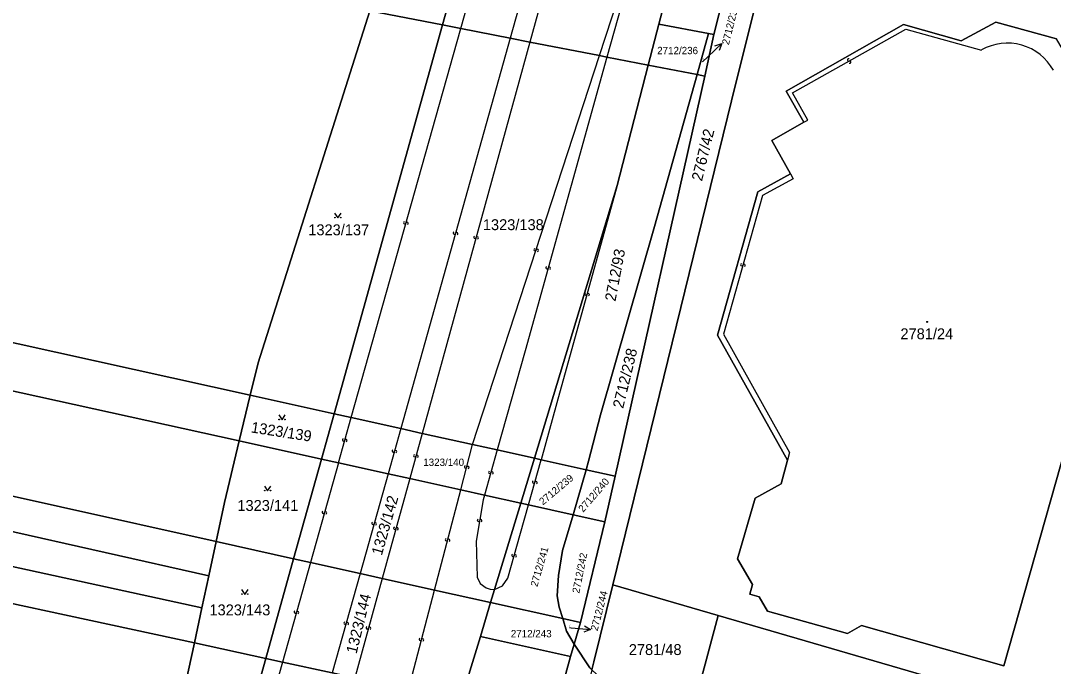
# Model space of a CAD drawing. Extents: x -596024 to -594475, y -1163820 to -1161957.
# Drawn here: x -595458.9 to -595298.2, y -1162184.4 to -1162083.9 of the extents above; entities that cross this region are included whole.
import ezdxf

# ---------------------------------------------------------------- set-up
doc = ezdxf.new("R2010")
doc.units = 0
for name, color, linetype in [('Level 1', 7, 'Continuous'), ('Level 13', 7, 'Continuous'), ('Level 3', 7, 'Continuous'), ('Level 4', 7, 'Continuous'), ('Level 5', 7, 'Continuous'), ('Level 57', 7, 'Continuous'), ('Level 60', 7, 'Continuous')]:
    doc.layers.add(name, color=color, linetype=linetype)

msp = doc.modelspace()

# ---------------------------------------------------------------- linework, layer by layer
at = {"layer": 'Level 1'}
for points in [[(-595366.74, -1162171.69), (-595347.56, -1162093.56), (-595333.91, -1162039.19), (-595332.78, -1162034.85)], [(-595385.78, -1162057.72), (-595393.25, -1162084.52)], [(-595359.57, -1162084.4), (-595354.15, -1162063.7)], [(-595351, -1162086.03), (-595345.7, -1162065.12)], [(-595404.57, -1162082.31), (-595421.96, -1162137.12), (-595423.19, -1162142.18)], [(-595393.25, -1162084.52), (-595404.57, -1162082.31)], [(-595393.25, -1162084.52), (-595410.14, -1162145.07)], [(-595393.25, -1162084.52), (-595390.42, -1162085.07)], [(-595390.42, -1162085.07), (-595382.7, -1162086.58)], [(-595361.22, -1162090.78), (-595359.57, -1162084.4)], [(-595359.57, -1162084.4), (-595351.83, -1162085.86)], [(-595255.68, -1162115.98), (-595277.18, -1162109.81), (-595285.73, -1162094.54), (-595294.54, -1162092.05), (-595297.65, -1162086.67), (-595307.1, -1162084.06), (-595312.49, -1162087.01), (-595321.47, -1162084.47), (-595339.77, -1162094.82), (-595336.98, -1162099.67)], [(-595382.7, -1162086.58), (-595379.64, -1162087.18)], [(-595379.64, -1162087.18), (-595368.8, -1162089.3)], [(-595351.83, -1162085.86), (-595353.63, -1162092.26)], [(-595352.42, -1162092.5), (-595351, -1162086.03)], [(-595351.83, -1162085.86), (-595351, -1162086.03)], [(-595368.8, -1162089.3), (-595367.65, -1162089.52)], [(-595367.65, -1162089.52), (-595361.22, -1162090.78)], [(-595366.06, -1162109.54), (-595361.22, -1162090.78)], [(-595361.22, -1162090.78), (-595353.63, -1162092.26)], [(-595370.9, -1162153.77), (-595370.51, -1162152.44), (-595368.66, -1162145.25), (-595360.26, -1162115.92), (-595353.63, -1162092.26)], [(-595352.42, -1162092.5), (-595366.35, -1162154.78)], [(-595353.63, -1162092.26), (-595352.42, -1162092.5)], [(-595336.98, -1162099.67), (-595341.96, -1162102.49), (-595339.09, -1162107.72)], [(-595339.09, -1162107.72), (-595344.15, -1162110.52), (-595350.46, -1162132.83), (-595339.54, -1162152.29)], [(-595378.94, -1162151.99), (-595366.06, -1162109.54)], [(-595529.52, -1162117.18), (-595471.58, -1162131.45), (-595423.19, -1162142.18)], [(-595424.9, -1162149.3), (-595473.29, -1162138.61), (-595531.85, -1162124.44)], [(-595608.74, -1162129.27), (-595574.69, -1162137.44), (-595478.13, -1162159.4), (-595429.64, -1162170.28)], [(-595430.71, -1162175.3), (-595479.35, -1162164.7), (-595575.71, -1162142.44), (-595610.67, -1162134.07)], [(-595339.54, -1162152.29), (-595340.54, -1162155.98), (-595344.6, -1162158.19), (-595347.3, -1162167.65), (-595344.98, -1162171.66), (-595345.4, -1162173.16), (-595343.93, -1162173.56), (-595342.65, -1162175.78), (-595330.22, -1162179.25), (-595328.01, -1162178.03), (-595305.84, -1162184.29), (-595292.09, -1162135.75)], [(-595536.86, -1162140.03), (-595477.03, -1162154.15), (-595428.5, -1162164.95)], [(-595423.19, -1162142.18), (-595424.9, -1162149.3)], [(-595410.14, -1162145.07), (-595423.19, -1162142.18)], [(-595412.11, -1162152.13), (-595410.14, -1162145.07)], [(-595410.14, -1162145.07), (-595407.49, -1162145.66)], [(-595407.49, -1162145.66), (-595399.75, -1162147.37)], [(-595399.75, -1162147.37), (-595396.42, -1162148.11)], [(-595396.42, -1162148.11), (-595388.56, -1162149.85)], [(-595424.9, -1162149.3), (-595427.2, -1162158.9), (-595428.5, -1162164.95)], [(-595424.9, -1162149.3), (-595412.11, -1162152.13)], [(-595388.56, -1162149.85), (-595384.74, -1162150.7)], [(-595384.74, -1162150.7), (-595378.94, -1162151.99)], [(-595416.43, -1162167.64), (-595412.11, -1162152.13)], [(-595412.11, -1162152.13), (-595409.47, -1162152.71)], [(-595409.47, -1162152.71), (-595401.73, -1162154.42)], [(-595381.07, -1162158.98), (-595378.94, -1162151.99)], [(-595378.94, -1162151.99), (-595377.9, -1162152.22)], [(-595377.9, -1162152.22), (-595370.9, -1162153.77)], [(-595401.73, -1162154.42), (-595398.36, -1162155.16)], [(-595372.93, -1162160.78), (-595370.9, -1162153.77)], [(-595370.9, -1162153.77), (-595366.35, -1162154.78)], [(-595431.88, -1162180.75), (-595481.06, -1162170.15), (-595542.01, -1162156.02)], [(-595398.36, -1162155.16), (-595390.42, -1162156.92)], [(-595367.99, -1162161.87), (-595366.35, -1162154.78)], [(-595390.42, -1162156.92), (-595386.71, -1162157.74)], [(-595386.71, -1162157.74), (-595381.07, -1162158.98)], [(-595385.15, -1162172.4), (-595381.07, -1162158.98)], [(-595381.07, -1162158.98), (-595379.87, -1162159.25)], [(-595379.87, -1162159.25), (-595372.93, -1162160.78)], [(-595374.52, -1162176.96), (-595375.07, -1162175.16), (-595375.41, -1162173.43), (-595375.22, -1162170.27), (-595374.55, -1162166.36), (-595372.93, -1162160.78)], [(-595372.93, -1162160.78), (-595367.99, -1162161.87)], [(-595367.99, -1162161.87), (-595371.78, -1162177.57)], [(-595428.5, -1162164.95), (-595429.64, -1162170.28)], [(-595428.5, -1162164.95), (-595416.43, -1162167.64)], [(-595420.76, -1162183.17), (-595416.43, -1162167.64)], [(-595416.43, -1162167.64), (-595413.82, -1162168.22)], [(-595413.82, -1162168.22), (-595406.08, -1162169.94)], [(-595429.64, -1162170.28), (-595430.71, -1162175.3)], [(-595406.08, -1162169.94), (-595402.64, -1162170.7)], [(-595402.64, -1162170.7), (-595394.51, -1162172.51)], [(-595385.78, -1162174.46), (-595385.15, -1162172.4)], [(-595366.74, -1162171.69), (-595369.68, -1162183.68), (-595369.99, -1162184.93)], [(-595366.74, -1162171.69), (-595350.31, -1162176.47)], [(-595394.51, -1162172.51), (-595385.78, -1162174.46)], [(-595430.71, -1162175.3), (-595431.88, -1162180.75)], [(-595387.35, -1162179.74), (-595385.78, -1162174.46)], [(-595385.78, -1162174.46), (-595374.52, -1162176.96)], [(-595371.78, -1162177.57), (-595374.52, -1162176.96)], [(-595372.78, -1162180.96), (-595373.93, -1162178.89), (-595374.52, -1162176.96)], [(-595353.12, -1162186.95), (-595350.31, -1162176.47)], [(-595350.31, -1162176.47), (-595282.98, -1162196.08)], [(-595371.78, -1162177.57), (-595372.78, -1162180.96)], [(-595388.79, -1162184.49), (-595387.35, -1162179.74)], [(-595373.34, -1162182.88), (-595387.35, -1162179.74)], [(-595431.88, -1162180.75), (-595437.24, -1162205.32)], [(-595431.88, -1162180.75), (-595420.76, -1162183.17)], [(-595372.78, -1162180.96), (-595373.34, -1162182.88)], [(-595372.78, -1162180.96), (-595370.33, -1162184.61), (-595369.99, -1162184.93)], [(-595427.5, -1162207.31), (-595420.76, -1162183.17)], [(-595420.76, -1162183.17), (-595418.17, -1162183.73)], [(-595373.34, -1162182.88), (-595374.6, -1162187.59)], [(-595418.17, -1162183.73), (-595410.42, -1162185.42)]]:
    msp.add_lwpolyline(points, dxfattribs=at)
at = {"layer": 'Level 13'}
for centre, start, end in [((-595330.03, -1162089.98), 66.6827, 298.7807), ((-595329.85, -1162090.3), 246.4683, 119.0583), ((-595399.14, -1162115.31), 111.6386, 343.7366), ((-595398.78, -1162115.41), 291.4242, 164.0142), ((-595391.41, -1162116.93), 111.4909, 344.0809), ((-595391.05, -1162117.03), 291.7053, 163.8033), ((-595388.21, -1162117.59), 111.7608, 344.3508), ((-595387.85, -1162117.69), 291.9753, 164.0733), ((-595378.85, -1162119.52), 109.2991, 341.3971), ((-595378.51, -1162119.64), 289.0846, 161.6746), ((-595376.99, -1162122.33), 111.5458, 344.1358), ((-595376.63, -1162122.43), 291.7602, 163.8582), ((-595346.66, -1162121.85), 111.3567, 343.9467), ((-595346.3, -1162121.95), 291.5711, 163.6691), ((-595370.93, -1162126.41), 111.6813, 344.2713), ((-595370.57, -1162126.51), 291.8958, 163.9938), ((-595408.66, -1162149.13), 111.6853, 343.7833), ((-595408.3, -1162149.23), 291.4708, 164.0608), ((-595400.92, -1162150.85), 111.4708, 344.0608), ((-595400.56, -1162150.95), 291.6853, 163.7833), ((-595397.57, -1162151.59), 111.7726, 344.3626), ((-595397.21, -1162151.69), 291.987, 164.085), ((-595389.67, -1162153.33), 112.6332, 344.7312), ((-595389.31, -1162153.43), 292.4187, 165.0087), ((-595385.9, -1162154.17), 111.5251, 344.1151), ((-595385.54, -1162154.27), 291.7395, 163.8375), ((-595379.06, -1162155.68), 111.7184, 343.8164), ((-595378.7, -1162155.78), 291.5039, 164.0939), ((-595411.82, -1162160.41), 111.4914, 344.0814), ((-595411.46, -1162160.51), 291.7058, 163.8038), ((-595404.08, -1162162.13), 111.501, 344.091), ((-595403.72, -1162162.23), 291.7154, 163.8134), ((-595400.68, -1162162.88), 111.7597, 344.3497), ((-595400.32, -1162162.98), 291.9742, 164.0722), ((-595387.66, -1162161.65), 117.3189, 349.9089), ((-595387.3, -1162161.71), 297.5334, 169.6314), ((-595392.65, -1162164.66), 112.6726, 344.7706), ((-595392.29, -1162164.76), 292.4581, 165.0481), ((-595382.28, -1162167.11), 111.4489, 343.5469), ((-595381.92, -1162167.21), 291.2345, 163.8245), ((-595416.18, -1162175.93), 111.4914, 344.0814), ((-595415.82, -1162176.03), 291.7058, 163.8038), ((-595408.43, -1162177.63), 111.4968, 344.0868), ((-595408.07, -1162177.73), 291.7113, 163.8093), ((-595404.96, -1162178.39), 111.7373, 344.3273), ((-595404.6, -1162178.49), 291.9518, 164.0498), ((-595396.72, -1162180.2), 112.6856, 344.7836), ((-595396.36, -1162180.3), 292.4712, 165.0612)]:
    msp.add_arc(centre, 0.184, start, end, dxfattribs=at)
at = {"layer": 'Level 3'}
for points in [[(-595390.42, -1162085.07), (-595382.87, -1162058.27)], [(-595375.17, -1162059.72), (-595382.7, -1162086.58)], [(-595372.23, -1162060.28), (-595379.64, -1162087.18)], [(-595368.8, -1162089.3), (-595360.08, -1162062.58)], [(-595360.08, -1162062.58), (-595363.12, -1162073.29), (-595367.65, -1162089.52)], [(-595407.49, -1162145.66), (-595390.42, -1162085.07)], [(-595336.98, -1162099.67), (-595336.38, -1162099.33), (-595338.77, -1162095.1), (-595321.1, -1162085.18), (-595309.34, -1162088.42)], [(-595382.7, -1162086.58), (-595399.75, -1162147.37)], [(-595379.64, -1162087.18), (-595396.42, -1162148.11)], [(-595388.56, -1162149.85), (-595368.8, -1162089.3)], [(-595367.65, -1162089.52), (-595373.22, -1162109.51), (-595380.41, -1162135.24), (-595384.74, -1162150.7)], [(-595339.09, -1162107.72), (-595338.68, -1162108.46), (-595343.42, -1162111.1), (-595349.53, -1162132.69), (-595339.21, -1162151.09), (-595339.54, -1162152.29)], [(-595366.06, -1162109.54), (-595375.43, -1162143.38), (-595377.9, -1162152.22)], [(-595409.47, -1162152.71), (-595407.49, -1162145.66)], [(-595399.75, -1162147.37), (-595401.73, -1162154.42)], [(-595396.42, -1162148.11), (-595398.36, -1162155.16)], [(-595390.42, -1162156.92), (-595388.56, -1162149.85)], [(-595384.74, -1162150.7), (-595386.71, -1162157.74)], [(-595409.47, -1162152.71), (-595413.82, -1162168.22)], [(-595379.87, -1162159.25), (-595377.9, -1162152.22)], [(-595401.73, -1162154.42), (-595406.08, -1162169.94)], [(-595398.36, -1162155.16), (-595402.64, -1162170.7)], [(-595394.51, -1162172.51), (-595390.42, -1162156.92)], [(-595386.71, -1162157.74), (-595386.92, -1162158.48), (-595388.03, -1162164.88), (-595387.85, -1162170.51), (-595387.4, -1162171.47), (-595386.48, -1162172.19), (-595385.85, -1162172.39), (-595385.15, -1162172.4)], [(-595385.15, -1162172.4), (-595383.89, -1162171.84), (-595383.1, -1162170.66), (-595381.1, -1162163.65), (-595379.87, -1162159.25)], [(-595413.82, -1162168.22), (-595418.17, -1162183.73)], [(-595406.08, -1162169.94), (-595410.42, -1162185.42)], [(-595402.64, -1162170.7), (-595406.91, -1162186.18)], [(-595398.57, -1162188), (-595394.51, -1162172.51)], [(-595418.17, -1162183.73), (-595424.95, -1162207.89)]]:
    msp.add_lwpolyline(points, dxfattribs=at)
msp.add_arc((-595305.29, -1162095.48), 8.14, 28.6322, 119.829, dxfattribs=at)
at = {"layer": 'Level 5'}
for points in [[(-595410.05, -1162113.82), (-595409.55, -1162114.57), (-595409.05, -1162113.82)], [(-595418.73, -1162145.25), (-595418.23, -1162146), (-595417.73, -1162145.25)], [(-595420.98, -1162156.33), (-595420.48, -1162157.08), (-595419.98, -1162156.33)], [(-595424.53, -1162172.43), (-595424.03, -1162173.18), (-595423.53, -1162172.43)]]:
    msp.add_lwpolyline(points, dxfattribs=at)
for centre, radius in [((-595410, -1162114.52), 0.05), ((-595409.1, -1162114.52), 0.05), ((-595317.8, -1162130.76), 0.09), ((-595317.8, -1162130.76), 0.0521), ((-595418.68, -1162145.95), 0.05), ((-595417.78, -1162145.95), 0.05), ((-595420.93, -1162157.03), 0.05), ((-595420.03, -1162157.03), 0.05), ((-595424.48, -1162173.13), 0.05), ((-595423.58, -1162173.13), 0.05)]:
    msp.add_circle(centre, radius, dxfattribs=at)
at = {"layer": 'Level 57'}
for p, q in [((-595351.95, -1162089.5), (-595349.78, -1162087.43)), ((-595352.76, -1162090.27), (-595351.95, -1162089.5)), ((-595373.49, -1162178.34), (-595373.2, -1162178.37)), ((-595373.2, -1162178.37), (-595370.22, -1162178.67))]:
    msp.add_line(p, q, dxfattribs=at)
for points in [[(-595350.84, -1162087.75), (-595349.78, -1162087.43), (-595350.16, -1162088.48)], [(-595371.17, -1162178.07), (-595370.22, -1162178.67), (-595371.27, -1162179.07)]]:
    msp.add_lwpolyline(points, dxfattribs=at)
at = {"layer": 'Level 60'}
for points in [[(-595282.98, -1162196.08), (-595350.31, -1162176.47), (-595366.74, -1162171.69), (-595347.56, -1162093.56), (-595333.91, -1162039.19), (-595332.78, -1162034.85), (-595330.6, -1162034.03), (-595319.23, -1162033.98), (-595308.02, -1162036.35), (-595300.3, -1162039.1), (-595285.09, -1162044.31)], [(-595297.65, -1162086.67), (-595307.1, -1162084.06), (-595312.49, -1162087.01), (-595321.47, -1162084.47), (-595339.77, -1162094.82), (-595336.98, -1162099.67), (-595341.96, -1162102.49), (-595339.09, -1162107.72), (-595344.15, -1162110.52), (-595350.46, -1162132.83), (-595339.54, -1162152.29), (-595340.54, -1162155.98), (-595344.6, -1162158.19), (-595347.3, -1162167.65), (-595344.98, -1162171.66), (-595345.4, -1162173.16), (-595343.93, -1162173.56), (-595342.65, -1162175.78), (-595330.22, -1162179.25), (-595328.01, -1162178.03), (-595305.84, -1162184.29), (-595292.09, -1162135.75)], [(-595292.09, -1162135.75), (-595305.84, -1162184.29), (-595328.01, -1162178.03), (-595330.22, -1162179.25), (-595342.65, -1162175.78), (-595343.93, -1162173.56), (-595345.4, -1162173.16), (-595344.98, -1162171.66), (-595347.3, -1162167.65), (-595344.6, -1162158.19), (-595340.54, -1162155.98), (-595339.54, -1162152.29), (-595350.46, -1162132.83), (-595344.15, -1162110.52), (-595339.09, -1162107.72), (-595341.96, -1162102.49), (-595336.98, -1162099.67), (-595339.77, -1162094.82), (-595321.47, -1162084.47), (-595312.49, -1162087.01), (-595307.1, -1162084.06), (-595297.65, -1162086.67)]]:
    msp.add_lwpolyline(points, dxfattribs=at)
for points in [[(-595338.5, -1162037.03), (-595332.78, -1162034.85), (-595333.91, -1162039.19), (-595347.56, -1162093.56), (-595366.74, -1162171.69), (-595369.68, -1162183.68), (-595369.99, -1162184.93), (-595370.33, -1162184.61), (-595372.78, -1162180.96), (-595371.78, -1162177.57), (-595367.99, -1162161.87), (-595366.35, -1162154.78), (-595352.42, -1162092.5), (-595351, -1162086.03), (-595345.7, -1162065.12), (-595344.32, -1162059.74)], [(-595398.58, -1162063.43), (-595395.96, -1162055.8), (-595385.78, -1162057.72), (-595393.25, -1162084.52), (-595404.57, -1162082.31), (-595402.55, -1162075.96), (-595400.52, -1162069.54)], [(-595359.57, -1162084.4), (-595361.22, -1162090.78), (-595367.65, -1162089.52), (-595368.8, -1162089.3), (-595379.64, -1162087.18), (-595382.7, -1162086.58), (-595390.42, -1162085.07), (-595393.25, -1162084.52), (-595385.78, -1162057.72), (-595382.87, -1162058.27), (-595375.17, -1162059.72), (-595372.23, -1162060.28), (-595360.08, -1162062.58), (-595354.15, -1162063.7)], [(-595404.57, -1162082.31), (-595421.96, -1162137.12), (-595423.19, -1162142.18), (-595471.58, -1162131.45), (-595529.52, -1162117.18), (-595510.72, -1162058.81), (-595457.21, -1162072.03)], [(-595351.83, -1162085.86), (-595359.57, -1162084.4), (-595354.15, -1162063.7), (-595346, -1162065.06), (-595345.7, -1162065.12), (-595351, -1162086.03)], [(-595421.96, -1162137.12), (-595404.57, -1162082.31), (-595393.25, -1162084.52), (-595410.14, -1162145.07), (-595423.19, -1162142.18)], [(-595366.06, -1162109.54), (-595378.94, -1162151.99), (-595384.74, -1162150.7), (-595388.56, -1162149.85), (-595396.42, -1162148.11), (-595399.75, -1162147.37), (-595407.49, -1162145.66), (-595410.14, -1162145.07), (-595393.25, -1162084.52), (-595390.42, -1162085.07), (-595382.7, -1162086.58), (-595379.64, -1162087.18), (-595368.8, -1162089.3), (-595367.65, -1162089.52), (-595361.22, -1162090.78)], [(-595361.22, -1162090.78), (-595359.57, -1162084.4), (-595351.83, -1162085.86), (-595353.63, -1162092.26)], [(-595351.83, -1162085.86), (-595351, -1162086.03), (-595352.42, -1162092.5), (-595353.63, -1162092.26)], [(-595378.94, -1162151.99), (-595366.06, -1162109.54), (-595361.22, -1162090.78), (-595353.63, -1162092.26), (-595360.26, -1162115.92), (-595368.66, -1162145.25), (-595370.51, -1162152.44), (-595370.9, -1162153.77), (-595377.9, -1162152.22)], [(-595353.63, -1162092.26), (-595352.42, -1162092.5), (-595366.35, -1162154.78), (-595370.9, -1162153.77), (-595370.51, -1162152.44), (-595368.66, -1162145.25), (-595360.26, -1162115.92)], [(-595423.19, -1162142.18), (-595424.9, -1162149.3), (-595473.29, -1162138.61), (-595531.85, -1162124.44), (-595600.24, -1162108.12), (-595597.3, -1162100.8), (-595569.1, -1162107.57), (-595529.52, -1162117.18), (-595471.58, -1162131.45)], [(-595573.84, -1162131.52), (-595536.86, -1162140.03), (-595477.03, -1162154.15), (-595428.5, -1162164.95), (-595429.64, -1162170.28), (-595478.13, -1162159.4), (-595574.69, -1162137.44), (-595608.74, -1162129.27), (-595606.56, -1162123.84)], [(-595424.9, -1162149.3), (-595427.2, -1162158.9), (-595428.5, -1162164.95), (-595477.03, -1162154.15), (-595536.86, -1162140.03), (-595531.85, -1162124.44), (-595473.29, -1162138.61)], [(-595610.67, -1162134.07), (-595608.74, -1162129.27), (-595574.69, -1162137.44), (-595478.13, -1162159.4), (-595429.64, -1162170.28), (-595430.71, -1162175.3), (-595479.35, -1162164.7), (-595575.71, -1162142.44)], [(-595577.06, -1162147.96), (-595612.93, -1162139.69), (-595610.67, -1162134.07), (-595575.71, -1162142.44), (-595479.35, -1162164.7), (-595430.71, -1162175.3), (-595431.88, -1162180.75), (-595481.06, -1162170.15), (-595542.01, -1162156.02)], [(-595424.9, -1162149.3), (-595423.19, -1162142.18), (-595410.14, -1162145.07), (-595412.11, -1162152.13)], [(-595378.94, -1162151.99), (-595381.07, -1162158.98), (-595386.71, -1162157.74), (-595390.42, -1162156.92), (-595398.36, -1162155.16), (-595401.73, -1162154.42), (-595409.47, -1162152.71), (-595412.11, -1162152.13), (-595410.14, -1162145.07), (-595407.49, -1162145.66), (-595399.75, -1162147.37), (-595396.42, -1162148.11), (-595388.56, -1162149.85), (-595384.74, -1162150.7)], [(-595427.2, -1162158.9), (-595424.9, -1162149.3), (-595412.11, -1162152.13), (-595416.43, -1162167.64), (-595428.5, -1162164.95)], [(-595416.43, -1162167.64), (-595412.11, -1162152.13), (-595409.47, -1162152.71), (-595401.73, -1162154.42), (-595398.36, -1162155.16), (-595390.42, -1162156.92), (-595386.71, -1162157.74), (-595381.07, -1162158.98), (-595385.15, -1162172.4), (-595385.78, -1162174.46), (-595394.51, -1162172.51), (-595402.64, -1162170.7), (-595406.08, -1162169.94), (-595413.82, -1162168.22)], [(-595381.07, -1162158.98), (-595378.94, -1162151.99), (-595377.9, -1162152.22), (-595370.9, -1162153.77), (-595372.93, -1162160.78), (-595379.87, -1162159.25)], [(-595370.9, -1162153.77), (-595366.35, -1162154.78), (-595367.99, -1162161.87), (-595372.93, -1162160.78)], [(-595431.88, -1162180.75), (-595437.24, -1162205.32), (-595516.52, -1162188.48), (-595550.02, -1162180.9), (-595542.01, -1162156.02), (-595481.06, -1162170.15)], [(-595375.07, -1162175.16), (-595374.52, -1162176.96), (-595385.78, -1162174.46), (-595385.15, -1162172.4), (-595381.07, -1162158.98), (-595379.87, -1162159.25), (-595372.93, -1162160.78), (-595374.55, -1162166.36), (-595375.22, -1162170.27), (-595375.41, -1162173.43)], [(-595372.93, -1162160.78), (-595367.99, -1162161.87), (-595371.78, -1162177.57), (-595374.52, -1162176.96), (-595375.07, -1162175.16), (-595375.41, -1162173.43), (-595375.22, -1162170.27), (-595374.55, -1162166.36)], [(-595428.5, -1162164.95), (-595416.43, -1162167.64), (-595420.76, -1162183.17), (-595431.88, -1162180.75), (-595430.71, -1162175.3), (-595429.64, -1162170.28)], [(-595385.78, -1162174.46), (-595387.35, -1162179.74), (-595388.79, -1162184.49), (-595389.6, -1162187.23), (-595390.35, -1162189.79), (-595395.48, -1162188.67), (-595398.57, -1162188), (-595406.91, -1162186.18), (-595410.42, -1162185.42), (-595418.17, -1162183.73), (-595420.76, -1162183.17), (-595416.43, -1162167.64), (-595413.82, -1162168.22), (-595406.08, -1162169.94), (-595402.64, -1162170.7), (-595394.51, -1162172.51)], [(-595350.31, -1162176.47), (-595353.12, -1162186.95), (-595354.39, -1162191.69), (-595362.25, -1162189.62), (-595364.12, -1162188.97), (-595366.58, -1162187.7), (-595368.61, -1162186.22), (-595369.99, -1162184.93), (-595369.68, -1162183.68), (-595366.74, -1162171.69)], [(-595385.78, -1162174.46), (-595374.52, -1162176.96), (-595373.93, -1162178.89), (-595372.78, -1162180.96), (-595373.34, -1162182.88), (-595387.35, -1162179.74)], [(-595374.52, -1162176.96), (-595371.78, -1162177.57), (-595372.78, -1162180.96), (-595373.93, -1162178.89)], [(-595341.8, -1162190.17), (-595353.12, -1162186.95), (-595350.31, -1162176.47), (-595282.98, -1162196.08), (-595316.76, -1162295.01), (-595349.09, -1162276.45), (-595374, -1162262.8), (-595372.41, -1162256.53), (-595355.74, -1162261.1), (-595354.35, -1162256.23), (-595351.24, -1162254), (-595331.37, -1162259.42), (-595328.22, -1162248.41), (-595323.28, -1162249.7), (-595314.64, -1162218.5), (-595319.47, -1162217.13), (-595315.78, -1162204.23), (-595337.5, -1162198.13), (-595338.22, -1162196.92), (-595336.74, -1162191.51)], [(-595387.35, -1162179.74), (-595373.34, -1162182.88), (-595374.6, -1162187.59), (-595375.79, -1162192.94), (-595383.2, -1162217.07), (-595395.33, -1162214.54), (-595398, -1162213.99), (-595390.35, -1162189.79), (-595389.6, -1162187.23), (-595388.79, -1162184.49)], [(-595437.24, -1162205.32), (-595431.88, -1162180.75), (-595420.76, -1162183.17), (-595427.5, -1162207.31)], [(-595386.68, -1162229.04), (-595383.2, -1162217.07), (-595375.79, -1162192.94), (-595374.6, -1162187.59), (-595373.34, -1162182.88), (-595372.78, -1162180.96), (-595370.33, -1162184.61), (-595369.99, -1162184.93), (-595370.84, -1162188.37), (-595381.91, -1162225.31), (-595385.63, -1162239.02), (-595389.6, -1162250.09), (-595390.72, -1162250.51), (-595392.95, -1162251.6), (-595391.31, -1162246.42), (-595388.94, -1162238.14)], [(-595390.35, -1162189.79), (-595398, -1162213.99), (-595402.27, -1162213.02), (-595405.59, -1162212.27), (-595413.74, -1162210.42), (-595417.21, -1162209.64), (-595424.95, -1162207.89), (-595427.5, -1162207.31), (-595420.76, -1162183.17), (-595418.17, -1162183.73), (-595410.42, -1162185.42), (-595406.91, -1162186.18), (-595398.57, -1162188), (-595395.48, -1162188.67)]]:
    msp.add_lwpolyline(points, close=True, dxfattribs=at)

# ---------------------------------------------------------------- texts
at = {"layer": 'Level 4'}
for s, height, p in [('2712/236', 1.14, (-595359.83, -1162089.07)), ('1323/137', 1.7, (-595414.15, -1162117.27)), ('1323/138', 1.7, (-595386.97, -1162116.47)), ('2781/24', 1.7, (-595321.96, -1162133.46)), ('1323/140', 1.14, (-595396.25, -1162153.18)), ('1323/141', 1.7, (-595425.19, -1162160.19)), ('1323/143', 1.7, (-595429.54, -1162176.45)), ('2712/243', 1.14, (-595382.62, -1162179.87)), ('2781/48', 1.7, (-595364.25, -1162182.63))]:
    msp.add_text(s, height=height, dxfattribs=at).set_placement(p)
for s, height, rotation, p in [('2712/237', 0.1, 76.0683, (-595352.76, -1162090.27)), ('2767/42', 1.7, 76.2073, (-595352.86, -1162108.93)), ('2712/93', 1.7, 79.205, (-595366.33, -1162127.65)), ('2712/238', 1.7, 76.4175, (-595365.13, -1162144.32)), ('1323/139', 1.7, 351.1696, (-595423.15, -1162147.96)), ('2712/239', 1.14, 39.9739, (-595377.62, -1162159.35)), ('2712/240', 1.14, 49.0945, (-595371.36, -1162160.49)), ('1323/142', 1.7, 74.0257, (-595402.71, -1162167.22)), ('2712/241', 1.14, 74.0344, (-595378.49, -1162172.09)), ('2712/242', 1.14, 78.6239, (-595371.96, -1162173.08)), ('1323/144', 1.7, 76.1088, (-595406.64, -1162182.53)), ('2712/244', 0.1, 75.4913, (-595373.49, -1162178.34))]:
    msp.add_text(s, height=height, rotation=rotation, dxfattribs=at).set_placement(p)
at = {"layer": 'Level 57'}
for s, rotation, p in [('2712/237', 76.0683, (-595348.67, -1162087.7)), ('2712/244', 75.4913, (-595369.12, -1162178.96))]:
    msp.add_text(s, height=1.14, rotation=rotation, dxfattribs=at).set_placement(p)

doc.saveas('drawing.dxf')
